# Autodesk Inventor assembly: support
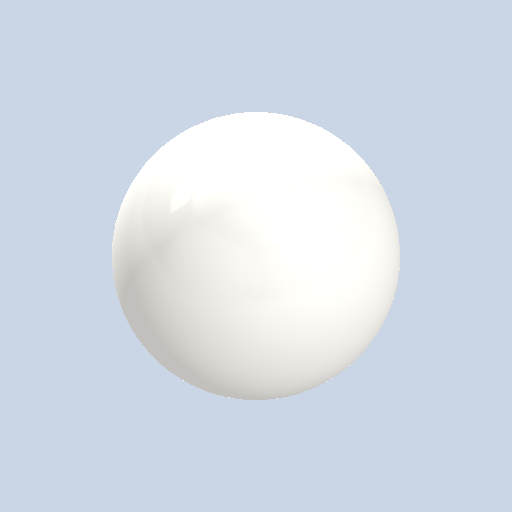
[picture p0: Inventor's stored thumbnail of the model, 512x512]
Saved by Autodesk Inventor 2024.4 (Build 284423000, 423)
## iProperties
Created: 2025-07
Part Number: support
Document SubType Name: Assembly
Designer: AdminForWorker
Title: support v1
Author: AdminForWorker
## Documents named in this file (2)
- c:\worker\convert-fusion-r03-cosv3\tmp\job-1\5\temp\files\c2717cec-cd30-4e2b-a2e5-52afbc4802da\support v1_2.iam
- c:\worker\convert-fusion-r03-cosv3\tmp\job-1\5\temp\files\c2717cec-cd30-4e2b-a2e5-52afbc4802da\Component1.ipt
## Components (1 placed, 1 different names)
1. Component1:1
